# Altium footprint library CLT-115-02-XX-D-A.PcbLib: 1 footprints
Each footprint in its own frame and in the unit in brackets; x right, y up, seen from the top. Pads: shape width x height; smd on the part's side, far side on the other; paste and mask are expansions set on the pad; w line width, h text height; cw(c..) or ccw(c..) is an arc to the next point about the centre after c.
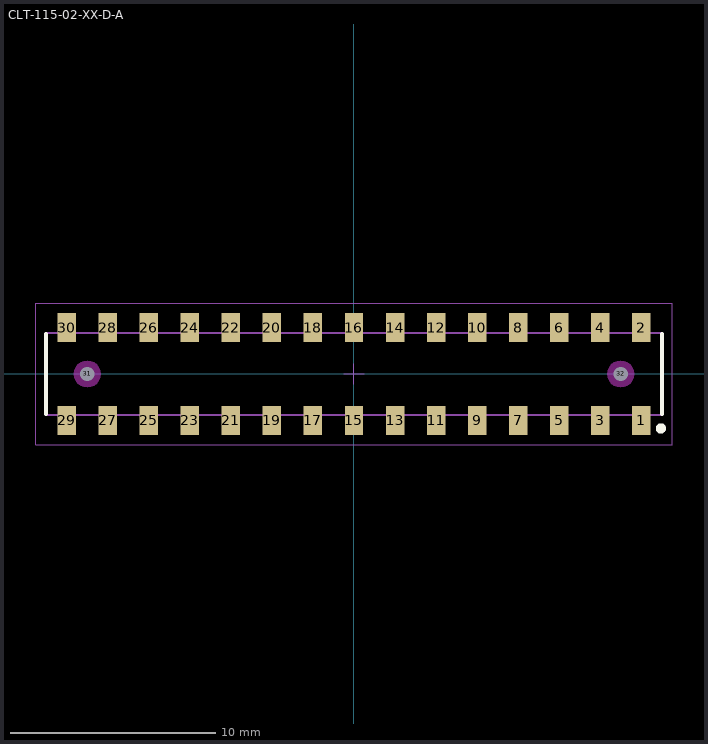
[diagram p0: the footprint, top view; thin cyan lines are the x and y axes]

## CLT-115-02-XX-D-A [mm] "2.00mm pitch, 30 pin, socket strip; low profile, w/alignment pins"
height 2.13
pads (32):
  rect 0.9x1.4 smd mask+0: 1(13.993,-2.261) 2(13.993,2.261) 3(11.994,-2.261) 4(11.994,2.261) 5(9.995,-2.261) 6(9.995,2.261) 7(7.996,-2.261) 8(7.996,2.261) 9(5.997,-2.261) 10(5.997,2.261) 11(3.998,-2.261) 12(3.998,2.261) 13(1.999,-2.261) 14(1.999,2.261) 15(0,-2.261) 16(0,2.261) 17(-1.999,-2.261) 18(-1.999,2.261) 19(-3.998,-2.261) 20(-3.998,2.261) 21(-5.997,-2.261) 22(-5.997,2.261) 23(-7.996,-2.261) 24(-7.996,2.261) 25(-9.995,-2.261) 26(-9.995,2.261) 27(-11.994,-2.261) 28(-11.994,2.261) 29(-13.993,-2.261) 30(-13.993,2.261)
  round 0.5 hole 0.7 unplated mask+0: 31(-12.993,0) 32(12.993,0)
Top Overlay:
  circle w0.25: c14.95,-2.65 r0.125
  lines w0.2: -15,-1.95 -15,1.95 ; 15,-1.95 15,1.95
Keep-Out Layer:
  pour cut-out: -12.337,0 -12.36,0.17 -12.425,0.328 -12.529,0.464 -12.665,0.568 -12.823,0.633 -12.993,0.656 -13.163,0.633 -13.321,0.568 -13.457,0.464 -13.561,0.328 -13.626,0.17 -13.649,0 -13.626,-0.17 -13.561,-0.328 -13.457,-0.464 -13.321,-0.568 -13.163,-0.633 -12.993,-0.656 -12.823,-0.633 -12.665,-0.568 -12.529,-0.464 -12.425,-0.328 -12.36,-0.17
  pour cut-out: 13.649,0 13.626,0.17 13.561,0.328 13.457,0.464 13.321,0.568 13.163,0.633 12.993,0.656 12.823,0.633 12.665,0.568 12.529,0.464 12.425,0.328 12.36,0.17 12.337,0 12.36,-0.17 12.425,-0.328 12.529,-0.464 12.665,-0.568 12.823,-0.633 12.993,-0.656 13.163,-0.633 13.321,-0.568 13.457,-0.464 13.561,-0.328 13.626,-0.17
Mechanical 12:
  lines w0.001: -15,-2 15,-2 15,2 -15,2 -15,-2
Mechanical 13:
  lines w0.1: -15,-2 15,-2 15,2 -15,2 -15,-2
  text ".Designator" at 0.254,0.254 h1.52
Mechanical 15:
  lines w0.05: -0.5,0 0.5,0 ; 0,-0.5 0,0.5 ; -15.5,-3.45 15.5,-3.45 15.5,3.45 -15.5,3.45 -15.5,-3.45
